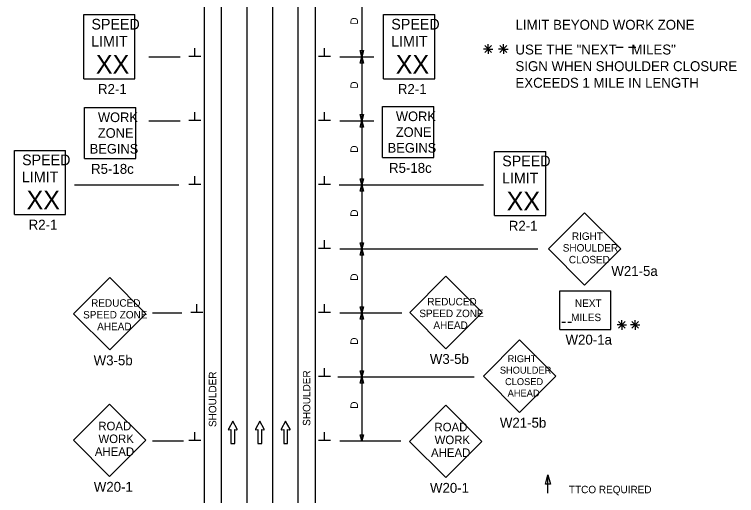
# Model space of a CAD drawing. Extents: x 16737 to 18479, y 6975 to 8225.
# Drawn here: x 16768 to 17445, y 7395 to 7846 of the extents above; entities that cross this region are included whole.
import ezdxf

# ---------------------------------------------------------------- set-up
doc = ezdxf.new("R2010")
doc.units = 0
for name, color, linetype in [('ALI_LEGAL_EX', 7, 'Continuous'), ('MT_SCRATCH_LEVEL_E', 7, 'Continuous'), ('PAVT_EDGE_EX', 7, 'Continuous'), ('TRAFFIC_SIGNS_PR', 7, 'Continuous'), ('TYPICAL_TEXT_DIMEN_EX', 7, 'Continuous'), ('TYPICAL_TEXT_DIMEN_PR', 7, 'Continuous')]:
    doc.layers.add(name, color=color, linetype=linetype)

msp = doc.modelspace()

# ---------------------------------------------------------------- linework, layer by layer
at = {"layer": 'ALI_LEGAL_EX'}
for points in [[(16985.65, 7825.29), (16985.65, 7800.29)], [(17009.65, 7825.29), (17009.65, 7800.29)], [(16985.65, 7725.29), (16985.65, 7700.29)], [(17009.65, 7725.29), (17009.65, 7700.29)], [(16985.65, 7625.29), (16985.65, 7600.29)], [(17009.65, 7625.29), (17009.65, 7600.29)], [(16985.65, 7525.29), (16985.65, 7500.29)], [(17009.65, 7525.29), (17009.65, 7500.29)], [(16985.65, 7425.29), (16985.65, 7400.29)], [(17009.65, 7425.29), (17009.65, 7400.29)]]:
    msp.add_lwpolyline(points, dxfattribs=at)
at = {"layer": 'MT_SCRATCH_LEVEL_E'}
for p, q in [((16972.46, 7464.59), (16968.34, 7457.35)), ((16972.46, 7464.59), (16968.34, 7457.35)), ((16976.6, 7457.35), (16972.46, 7464.59)), ((16976.6, 7457.35), (16972.46, 7464.59)), ((16997.88, 7464.59), (16993.77, 7457.35)), ((16997.88, 7464.59), (16993.77, 7457.35)), ((17002.03, 7457.35), (16997.88, 7464.59)), ((17002.03, 7457.35), (16997.88, 7464.59)), ((17022.09, 7464.59), (17017.98, 7457.35)), ((17022.09, 7464.59), (17017.98, 7457.35)), ((17026.24, 7457.35), (17022.09, 7464.59)), ((17026.24, 7457.35), (17022.09, 7464.59)), ((16968.83, 7456.67), (16970.6, 7456.99)), ((16968.83, 7456.67), (16970.6, 7456.99)), ((16970.6, 7456.99), (16970.6, 7443.73)), ((16970.6, 7456.99), (16970.6, 7443.73)), ((16974.35, 7443.73), (16974.35, 7456.99)), ((16974.35, 7456.99), (16976.12, 7456.67)), ((16974.35, 7443.73), (16974.35, 7456.99)), ((16974.35, 7456.99), (16976.12, 7456.67)), ((16994.25, 7456.67), (16996.03, 7456.99)), ((16994.25, 7456.67), (16996.03, 7456.99)), ((16996.03, 7456.99), (16996.03, 7443.73)), ((16996.03, 7456.99), (16996.03, 7443.73)), ((16999.77, 7443.73), (16999.77, 7456.99)), ((16999.77, 7456.99), (17001.55, 7456.67)), ((16999.77, 7443.73), (16999.77, 7456.99)), ((16999.77, 7456.99), (17001.55, 7456.67)), ((17018.47, 7456.67), (17020.24, 7456.99)), ((17018.47, 7456.67), (17020.24, 7456.99)), ((17020.24, 7456.99), (17020.24, 7443.73)), ((17020.24, 7456.99), (17020.24, 7443.73)), ((17023.98, 7443.73), (17023.98, 7456.99)), ((17023.98, 7456.99), (17025.76, 7456.67)), ((17023.98, 7443.73), (17023.98, 7456.99)), ((17023.98, 7456.99), (17025.76, 7456.67)), ((16970.6, 7443.73), (16974.35, 7443.73)), ((16970.6, 7443.73), (16974.35, 7443.73)), ((16996.03, 7443.73), (16999.77, 7443.73)), ((16996.03, 7443.73), (16999.77, 7443.73)), ((17020.24, 7443.73), (17023.98, 7443.73)), ((17020.24, 7443.73), (17023.98, 7443.73))]:
    msp.add_line(p, q, dxfattribs=at)
for centre, start, end in [((16968.75, 7457.13), 150.42484, 279.96381), ((16968.75, 7457.13), 150.42484, 279.96381), ((16976.19, 7457.13), 260.03619, 29.77312), ((16976.19, 7457.13), 260.03619, 29.77312), ((16994.18, 7457.13), 150.42484, 279.96381), ((16994.18, 7457.13), 150.42484, 279.96381), ((17001.62, 7457.13), 260.03619, 29.77312), ((17001.62, 7457.13), 260.03619, 29.77312), ((17018.39, 7457.13), 150.42484, 279.96381), ((17018.39, 7457.13), 150.42484, 279.96381), ((17025.83, 7457.13), 260.03619, 29.77312), ((17025.83, 7457.13), 260.03619, 29.77312)]:
    msp.add_arc(centre, 0.463, start, end, dxfattribs=at)
at = {"layer": 'PAVT_EDGE_EX'}
for p, q in [((16985.65, 8211.96), (16985.65, 7344.79)), ((17009.65, 8211.96), (17009.65, 7344.79)), ((16985.65, 8097.28), (16985.65, 7344.79)), ((17009.65, 8097.28), (17009.65, 7344.79)), ((16945.65, 7942.5), (16945.65, 7344.79)), ((16961.65, 7942.41), (16961.65, 7344.79)), ((17033.65, 7942.16), (17033.65, 7344.79)), ((17049.65, 7942.41), (17049.65, 7344.79))]:
    msp.add_line(p, q, dxfattribs=at)
at = {"layer": 'TRAFFIC_SIGNS_PR'}
for p, q in [((16832.67, 7845.71), (16880.67, 7845.71)), ((16832.67, 7785.71), (16832.67, 7845.71)), ((16880.67, 7785.71), (16880.67, 7845.71)), ((17114.03, 7845.71), (17162.03, 7845.71)), ((17114.03, 7785.71), (17114.03, 7845.71)), ((17162.03, 7785.71), (17162.03, 7845.71)), ((16832.67, 7785.71), (16880.67, 7785.71)), ((17114.03, 7785.71), (17162.03, 7785.71)), ((16833.49, 7710.82), (16833.49, 7758.82)), ((16833.49, 7758.82), (16881.49, 7758.82)), ((16881.49, 7710.82), (16881.49, 7758.82)), ((17113.05, 7711.73), (17113.05, 7759.73)), ((17113.05, 7759.73), (17161.05, 7759.73)), ((17161.05, 7711.73), (17161.05, 7759.73)), ((16767.63, 7718.54), (16815.63, 7718.54)), ((16767.63, 7658.54), (16767.63, 7718.54)), ((16815.63, 7658.54), (16815.63, 7718.54)), ((17218.1, 7717.51), (17266.1, 7717.51)), ((17218.1, 7657.51), (17218.1, 7717.51)), ((17266.1, 7657.51), (17266.1, 7717.51)), ((16833.49, 7710.82), (16881.49, 7710.82)), ((17113.05, 7711.73), (17161.05, 7711.73)), ((16767.63, 7658.54), (16815.63, 7658.54)), ((17218.1, 7657.51), (17266.1, 7657.51)), ((17302.61, 7660.13), (17268.67, 7626.19)), ((17336.55, 7626.19), (17302.61, 7660.13)), ((17268.67, 7626.19), (17302.61, 7592.25)), ((17302.61, 7592.25), (17336.55, 7626.19)), ((16857, 7599.3), (16823.06, 7565.36)), ((16890.94, 7565.36), (16857, 7599.3)), ((17172.45, 7600.52), (17138.51, 7566.58)), ((17206.39, 7566.58), (17172.45, 7600.52)), ((17279.26, 7550.78), (17279.26, 7586.78)), ((17279.26, 7586.78), (17327.26, 7586.78)), ((17327.26, 7550.78), (17327.26, 7586.78)), ((16823.06, 7565.36), (16857, 7531.42)), ((16857, 7531.42), (16890.94, 7565.36)), ((17138.51, 7566.58), (17172.45, 7532.64)), ((17172.45, 7532.64), (17206.39, 7566.58)), ((17281.12, 7557.38), (17284.62, 7557.38)), ((17286.92, 7557.38), (17290.42, 7557.38)), ((17279.26, 7550.78), (17327.26, 7550.78)), ((17241.65, 7540.79), (17207.71, 7506.85)), ((17275.59, 7506.85), (17241.65, 7540.79)), ((17207.71, 7506.85), (17241.65, 7472.91)), ((17241.65, 7472.91), (17275.59, 7506.85)), ((16856.87, 7480.71), (16822.93, 7446.77)), ((16890.81, 7446.77), (16856.87, 7480.71)), ((17172.29, 7479.73), (17138.35, 7445.78)), ((17206.23, 7445.78), (17172.29, 7479.73)), ((16822.93, 7446.77), (16856.87, 7412.83)), ((16856.87, 7412.83), (16890.81, 7446.77)), ((17138.35, 7445.78), (17172.29, 7411.84)), ((17172.29, 7411.84), (17206.23, 7445.78))]:
    msp.add_line(p, q, dxfattribs=at)
at = {"layer": 'TYPICAL_TEXT_DIMEN_EX'}
for p, q in [((17331.74, 7815.34), (17338.74, 7815.34)), ((17343.69, 7815.18), (17350.69, 7815.18))]:
    msp.add_line(p, q, dxfattribs=at)
at = {"layer": 'TYPICAL_TEXT_DIMEN_PR'}
for p, q in [((17093.65, 7866.13), (17093.65, 7806.13)), ((16937.02, 7806.56), (16937.02, 7814.34)), ((17058.58, 7806.56), (17058.58, 7814.34)), ((17093.65, 7806.13), (17092.08, 7811.99)), ((17092.08, 7811.99), (17093.65, 7811.99)), ((17093.65, 7811.99), (17095.22, 7811.99)), ((17095.22, 7811.99), (17093.65, 7806.13)), ((17212.15, 7813.52), (17207.62, 7813.52)), ((17208.97, 7816.71), (17215.34, 7810.33)), ((17215.34, 7816.71), (17208.97, 7810.33)), ((17212.15, 7813.52), (17212.15, 7817.98)), ((17212.15, 7813.52), (17215.34, 7813.52)), ((17212.15, 7813.52), (17216.63, 7813.52)), ((17212.15, 7813.52), (17212.15, 7809.02)), ((17226.37, 7813.52), (17221.84, 7813.52)), ((17223.19, 7816.71), (17229.56, 7810.33)), ((17229.56, 7816.71), (17223.19, 7810.33)), ((17226.37, 7813.52), (17226.37, 7817.98)), ((17226.37, 7813.52), (17229.56, 7813.52)), ((17226.37, 7813.52), (17230.85, 7813.52)), ((17226.37, 7813.52), (17226.37, 7809.02)), ((16893.76, 7806.13), (16923.12, 7806.13)), ((16942.65, 7806.56), (16931.4, 7806.56)), ((17064.21, 7806.56), (17052.96, 7806.56)), ((17072.81, 7806.13), (17104.89, 7806.13)), ((17092.08, 7800.27), (17093.65, 7806.13)), ((17093.65, 7806.13), (17093.65, 7746.13)), ((17093.65, 7806.13), (17095.22, 7800.27)), ((17093.65, 7800.27), (17092.08, 7800.27)), ((17095.22, 7800.27), (17093.65, 7800.27)), ((16937.02, 7746.56), (16937.02, 7754.34)), ((17058.58, 7746.56), (17058.58, 7754.34)), ((17093.65, 7746.13), (17092.08, 7751.99)), ((17092.08, 7751.99), (17093.65, 7751.99)), ((17093.65, 7751.99), (17095.22, 7751.99)), ((17095.22, 7751.99), (17093.65, 7746.13)), ((16893.76, 7746.13), (16923.12, 7746.13)), ((16942.65, 7746.56), (16931.4, 7746.56)), ((17064.21, 7746.56), (17052.96, 7746.56)), ((17072.81, 7746.13), (17104.89, 7746.13)), ((17092.08, 7740.27), (17093.65, 7746.13)), ((17093.65, 7746.13), (17093.65, 7686.13)), ((17093.65, 7746.13), (17095.22, 7740.27)), ((17093.65, 7740.27), (17092.08, 7740.27)), ((17095.22, 7740.27), (17093.65, 7740.27)), ((16937.02, 7686.56), (16937.02, 7694.34)), ((17058.58, 7686.56), (17058.58, 7694.34)), ((17093.65, 7686.13), (17092.08, 7691.99)), ((17092.08, 7691.99), (17093.65, 7691.99)), ((17093.65, 7691.99), (17095.22, 7691.99)), ((17095.22, 7691.99), (17093.65, 7686.13)), ((16823.87, 7686.13), (16921.99, 7686.13)), ((16942.65, 7686.56), (16931.4, 7686.56)), ((17064.21, 7686.56), (17052.96, 7686.56)), ((17072.33, 7686.13), (17207.84, 7686.13)), ((17092.08, 7680.27), (17093.65, 7686.13)), ((17093.65, 7686.13), (17093.65, 7626.13)), ((17093.65, 7686.13), (17095.22, 7680.27)), ((17093.65, 7680.27), (17092.08, 7680.27)), ((17095.22, 7680.27), (17093.65, 7680.27)), ((17058.58, 7626.56), (17058.58, 7634.34)), ((17093.65, 7626.13), (17092.08, 7631.99)), ((17092.08, 7631.99), (17093.65, 7631.99)), ((17093.65, 7631.99), (17095.22, 7631.99)), ((17095.22, 7631.99), (17093.65, 7626.13)), ((17064.21, 7626.56), (17052.96, 7626.56)), ((17072.81, 7626.13), (17258.56, 7626.13)), ((17092.08, 7620.27), (17093.65, 7626.13)), ((17093.65, 7626.13), (17093.65, 7566.13)), ((17093.65, 7626.13), (17095.22, 7620.27)), ((17093.65, 7620.27), (17092.08, 7620.27)), ((17095.22, 7620.27), (17093.65, 7620.27)), ((16938.63, 7566.56), (16938.63, 7574.34)), ((17058.58, 7566.56), (17058.58, 7574.34)), ((17093.65, 7566.13), (17092.08, 7571.99)), ((17092.08, 7571.99), (17093.65, 7571.99)), ((17093.65, 7571.99), (17095.22, 7571.99)), ((17095.22, 7571.99), (17093.65, 7566.13)), ((16897.22, 7566.13), (16924.73, 7566.13)), ((16944.25, 7566.56), (16933, 7566.56)), ((17064.21, 7566.56), (17052.96, 7566.56)), ((17072.81, 7566.13), (17130.95, 7566.13)), ((17092.08, 7560.27), (17093.65, 7566.13)), ((17093.65, 7566.13), (17093.65, 7506.13)), ((17093.65, 7566.13), (17095.22, 7560.27)), ((17093.65, 7560.27), (17092.08, 7560.27)), ((17095.22, 7560.27), (17093.65, 7560.27)), ((17337.54, 7554.92), (17333.01, 7554.92)), ((17334.36, 7558.11), (17340.73, 7551.74)), ((17340.73, 7558.11), (17334.36, 7551.74)), ((17337.54, 7554.92), (17337.54, 7559.38)), ((17337.54, 7554.92), (17340.73, 7554.92)), ((17337.54, 7554.92), (17342.02, 7554.92)), ((17337.54, 7554.92), (17337.54, 7550.42)), ((17350.04, 7554.92), (17345.51, 7554.92)), ((17346.85, 7558.11), (17353.23, 7551.74)), ((17353.23, 7558.11), (17346.85, 7551.74)), ((17350.04, 7554.92), (17350.04, 7559.38)), ((17350.04, 7554.92), (17353.23, 7554.92)), ((17350.04, 7554.92), (17354.52, 7554.92)), ((17350.04, 7554.92), (17350.04, 7550.42)), ((17058.58, 7506.56), (17058.58, 7514.34)), ((17093.65, 7506.13), (17092.08, 7511.99)), ((17092.08, 7511.99), (17093.65, 7511.99)), ((17093.65, 7511.99), (17095.22, 7511.99)), ((17095.22, 7511.99), (17093.65, 7506.13)), ((17064.21, 7506.56), (17052.96, 7506.56)), ((17071.2, 7506.13), (17199.05, 7506.13)), ((17092.08, 7500.27), (17093.65, 7506.13)), ((17093.65, 7500.27), (17092.08, 7500.27)), ((17093.65, 7506.13), (17093.65, 7446.13)), ((17093.65, 7506.13), (17095.22, 7500.27)), ((17095.22, 7500.27), (17093.65, 7500.27)), ((16937.02, 7446.56), (16937.02, 7454.34)), ((17058.58, 7446.56), (17058.58, 7454.34)), ((16897.22, 7446.13), (16926.19, 7446.13)), ((16942.65, 7446.56), (16931.4, 7446.56)), ((17064.21, 7446.56), (17052.96, 7446.56)), ((17072.81, 7446.13), (17130.29, 7446.13)), ((17093.65, 7446.13), (17092.08, 7451.99)), ((17092.08, 7451.99), (17093.65, 7451.99)), ((17093.65, 7451.99), (17095.22, 7451.99)), ((17095.22, 7451.99), (17093.65, 7446.13)), ((17265.82, 7405.59), (17268.17, 7414.38)), ((17268.17, 7397.26), (17268.17, 7414.38)), ((17268.17, 7414.38), (17270.53, 7405.59)), ((17268.17, 7405.59), (17265.82, 7405.59)), ((17270.53, 7405.59), (17268.17, 7405.59))]:
    msp.add_line(p, q, dxfattribs=at)

# ---------------------------------------------------------------- texts
at = {"layer": 'TRAFFIC_SIGNS_PR'}
for s, height, p in [('SPEED', 10, (16839.88, 7831.79)), ('SPEED', 10, (17121.24, 7831.79)), ('LIMIT', 10, (16839.67, 7815.79)), ('LIMIT', 10, (17121.04, 7815.79)), ('XX', 17.538, (16844.06, 7790.41)), ('XX', 17.538, (17125.42, 7790.41)), ('R2-1', 9.3, (16846.01, 7771.41)), ('R2-1', 9.3, (17127.38, 7771.41)), ('WORK', 9.021, (16845.99, 7745.03)), ('WORK', 9.021, (17125.55, 7745.93)), ('ZONE', 9.021, (16845.84, 7730.27)), ('ZONE', 9.021, (17125.4, 7731.17)), ('BEGINS', 9.021, (16838.25, 7715.51)), ('BEGINS', 9.021, (17117.81, 7716.41)), ('SPEED', 10, (16774.84, 7704.62)), ('SPEED', 10, (17225.31, 7703.59)), ('R5-18c', 9.3, (16839.51, 7696.52)), ('R5-18c', 9.3, (17119.06, 7697.43)), ('LIMIT', 10, (16774.64, 7688.62)), ('LIMIT', 10, (17225.1, 7687.59)), ('XX', 17.538, (16779.02, 7663.24)), ('XX', 17.538, (17229.49, 7662.21)), ('R2-1', 9.3, (16780.97, 7644.24)), ('R2-1', 9.3, (17231.44, 7643.21)), ('RIGHT', 7, (17290.66, 7634.64)), ('SHOULDER', 7, (17282.09, 7623.64)), ('CLOSED', 7, (17287.8, 7612.64)), ('W21-5a', 9.3, (17327.67, 7600.81)), ('REDUCED', 7, (16839.57, 7571.99)), ('REDUCED', 7, (17155.02, 7573.22)), ('NEXT', 7, (17293.52, 7571.78)), ('SPEED ZONE', 7, (16832.06, 7560.99)), ('SPEED ZONE', 7, (17147.52, 7562.22)), ('   MILES', 7, (17282.18, 7558.48)), ('AHEAD', 7, (16845.26, 7549.99)), ('AHEAD', 7, (17160.72, 7551.22)), ('W20-1a', 9.3, (17284.69, 7536.48)), ('W3-5b', 9.3, (17157.39, 7518.34)), ('W3-5b', 9.3, (16841.94, 7517.12)), ('RIGHT', 6.5, (17230.33, 7520.02)), ('SHOULDER', 6.5, (17223.06, 7509.27)), ('CLOSED', 6.5, (17227.94, 7498.52)), ('AHEAD', 6.5, (17230.39, 7487.77)), ('W21-5b', 9.3, (17223.1, 7458.61)), ('ROAD', 8, (16846.3, 7456.19)), ('ROAD', 8, (17161.72, 7455.2)), ('WORK', 8, (16846.43, 7444.19)), ('WORK', 8, (17161.85, 7443.2)), ('AHEAD', 8, (16843.07, 7432.19)), ('AHEAD', 8, (17158.49, 7431.2)), ('W20-1', 9.3, (16842.08, 7398.53)), ('W20-1', 9.3, (17157.5, 7397.55))]:
    msp.add_text(s, height=height, dxfattribs=at).set_placement(p)
at = {"layer": 'TYPICAL_TEXT_DIMEN_EX'}
for s, p in [('LIMIT BEYOND WORK ZONE', (17237.78, 7831.58)), ('USE THE "NEXT    MILES"', (17237.7, 7808.38)), ('SIGN WHEN SHOULDER CLOSURE', (17237.7, 7792.78)), ('EXCEEDS 1 MILE IN LENGTH', (17237.7, 7777.18))]:
    msp.add_text(s, height=9.3, dxfattribs=at).set_placement(p)
at = {"layer": 'TYPICAL_TEXT_DIMEN_PR'}
for s, p in [('D', (17089.92, 7836.37)), ('D', (17089.92, 7776.37)), ('D', (17089.92, 7716.37)), ('D', (17089.92, 7656.37)), ('D', (17089.92, 7596.37)), ('D', (17089.92, 7536.37)), ('SHOULDER', (16957.01, 7459.24)), ('SHOULDER', (17045.24, 7460.3)), ('D', (17089.92, 7476.37))]:
    msp.add_text(s, height=7, rotation=90, dxfattribs=at).set_placement(p)
msp.add_text('TTCO REQUIRED', height=7, dxfattribs=at).set_placement((17287.87, 7397.17))

doc.saveas('drawing.dxf')
